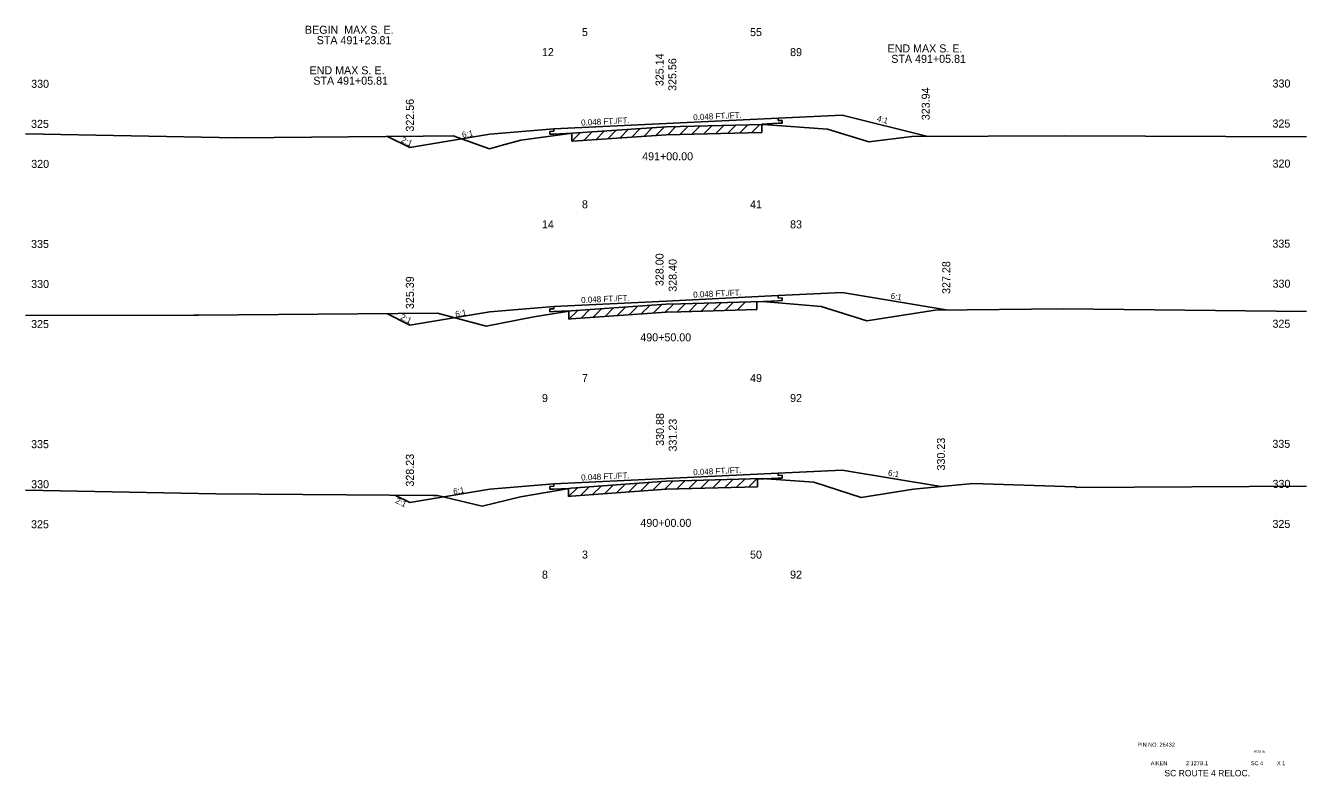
# Model space of a CAD drawing. Extents: x 2967 to 4323, y -3677 to -817.
# Drawn here: x 3188.8 to 3348.8, y -3580.8 to -3487.1 of the extents above; entities that cross this region are included whole.
import ezdxf

# ---------------------------------------------------------------- set-up
doc = ezdxf.new("R2010")
doc.units = 0
for name, color, linetype in [('Level 1', 7, 'Continuous'), ('Level 10', 7, 'Continuous'), ('Level 11', 7, 'Continuous'), ('Level 12', 7, 'Continuous'), ('Level 20', 7, 'Continuous'), ('Level 3', 7, 'Continuous'), ('Level 32', 7, 'Continuous'), ('Level 33', 7, 'Continuous'), ('Level 59', 7, 'Continuous'), ('Level 6', 7, 'Continuous'), ('Level 60', 7, 'Continuous'), ('Level 61', 7, 'Continuous'), ('Level 7', 7, 'Continuous')]:
    doc.layers.add(name, color=color, linetype=linetype)

msp = doc.modelspace()

# ---------------------------------------------------------------- linework, layer by layer
at = {"layer": 'Level 11'}
for p, q in [((3282.76, -3498.91), (3282.76, -3498.61)), ((3283.26, -3498.88), (3282.76, -3498.91)), ((3283.26, -3499.22), (3283.26, -3498.88)), ((3254.76, -3500.25), (3254.26, -3500.28)), ((3254.26, -3500.28), (3254.26, -3500.62)), ((3254.26, -3500.62), (3254.76, -3500.59)), ((3254.76, -3499.95), (3254.76, -3500.25)), ((3282.76, -3499.25), (3283.26, -3499.22)), ((3282.76, -3521.07), (3282.76, -3520.77)), ((3283.26, -3521.05), (3282.76, -3521.07)), ((3282.76, -3521.41), (3283.26, -3521.39)), ((3283.26, -3521.39), (3283.26, -3521.05)), ((3254.76, -3522.42), (3254.26, -3522.44)), ((3254.26, -3522.44), (3254.26, -3522.78)), ((3254.26, -3522.78), (3254.76, -3522.76)), ((3254.76, -3522.12), (3254.76, -3522.42)), ((3282.76, -3543.24), (3282.76, -3542.94)), ((3283.26, -3543.21), (3282.76, -3543.24)), ((3282.76, -3543.58), (3283.26, -3543.55)), ((3283.26, -3543.55), (3283.26, -3543.21)), ((3254.76, -3544.58), (3254.26, -3544.61)), ((3254.26, -3544.61), (3254.26, -3544.95)), ((3254.26, -3544.95), (3254.76, -3544.92)), ((3254.76, -3544.28), (3254.76, -3544.58))]:
    msp.add_line(p, q, dxfattribs=at)
at = {"layer": 'Level 12'}
for p, q in [((3256.98, -3500.49), (3254.76, -3500.59)), ((3256.98, -3500.5), (3256.98, -3500.49)), ((3280.72, -3499.35), (3282.76, -3499.25)), ((3280.72, -3499.39), (3280.72, -3499.35)), ((3280.12, -3521.54), (3282.76, -3521.41)), ((3280.12, -3521.52), (3280.12, -3521.54)), ((3256.64, -3522.67), (3254.76, -3522.76)), ((3256.64, -3522.71), (3256.64, -3522.67)), ((3280.17, -3543.7), (3282.76, -3543.58)), ((3280.17, -3543.64), (3280.17, -3543.7)), ((3256.58, -3544.84), (3254.76, -3544.92)), ((3256.58, -3544.87), (3256.58, -3544.84))]:
    msp.add_line(p, q, dxfattribs=at)
at = {"layer": 'Level 59'}
for p, q in [((3268.76, -3499.28), (3282.76, -3498.61)), ((3254.76, -3499.95), (3268.76, -3499.28)), ((3254.76, -3522.12), (3268.76, -3521.45)), ((3268.76, -3521.45), (3282.76, -3520.77)), ((3254.76, -3544.28), (3268.76, -3543.61)), ((3268.76, -3543.61), (3282.76, -3542.94))]:
    msp.add_line(p, q, dxfattribs=at)
at = {"layer": 'Level 6'}
for p, q in [((3282.76, -3498.61), (3290.76, -3498.22)), ((3246.76, -3500.62), (3254.76, -3499.95)), ((3282.76, -3520.77), (3290.76, -3520.39)), ((3246.76, -3522.78), (3254.76, -3522.12)), ((3282.76, -3542.94), (3290.76, -3542.55)), ((3246.76, -3544.95), (3254.76, -3544.28))]:
    msp.add_line(p, q, dxfattribs=at)
at = {"layer": 'Level 60'}
for p, q in [((3188.76, -3500.58), (3215.13, -3501.08)), ((3250.62, -3501.34), (3257.09, -3500.49)), ((3257.09, -3500.49), (3265.68, -3499.91)), ((3265.68, -3499.91), (3268.82, -3499.7)), ((3268.82, -3499.7), (3280.89, -3499.39)), ((3280.89, -3499.39), (3288.93, -3499.98)), ((3288.93, -3499.98), (3294.11, -3501.57)), ((3215.13, -3501.08), (3238.42, -3500.85)), ((3238.42, -3500.85), (3242.19, -3500.82)), ((3242.19, -3500.82), (3246.73, -3502.44)), ((3246.73, -3502.44), (3248.17, -3502.03)), ((3248.17, -3502.03), (3250.62, -3501.34)), ((3294.11, -3501.57), (3299.48, -3500.91)), ((3299.48, -3500.91), (3318.6, -3500.81)), ((3318.6, -3500.81), (3348.76, -3500.96)), ((3270.6, -3521.79), (3280.8, -3521.5)), ((3280.8, -3521.5), (3288.14, -3522.12)), ((3210.38, -3523.22), (3240.23, -3522.95)), ((3240.23, -3522.95), (3246.31, -3524.6)), ((3252.25, -3523.42), (3256.92, -3522.66)), ((3256.92, -3522.66), (3268.76, -3521.84)), ((3268.76, -3521.84), (3270.6, -3521.79)), ((3288.14, -3522.12), (3293.83, -3523.91)), ((3293.83, -3523.91), (3302.38, -3522.57)), ((3302.38, -3522.57), (3318.4, -3522.43)), ((3318.4, -3522.43), (3348.76, -3522.75)), ((3188.76, -3523.27), (3209.77, -3523.2)), ((3209.77, -3523.2), (3210.38, -3523.22)), ((3246.31, -3524.6), (3252.25, -3523.42)), ((3256.91, -3544.81), (3268.76, -3543.96)), ((3268.76, -3543.96), (3271.99, -3543.87)), ((3271.99, -3543.87), (3280.71, -3543.62)), ((3280.71, -3543.62), (3287.23, -3544.05)), ((3188.76, -3545.08), (3212.53, -3545.52)), ((3212.53, -3545.52), (3239.68, -3545.72)), ((3250.6, -3545.91), (3256.91, -3544.81)), ((3287.23, -3544.05), (3293.16, -3545.99)), ((3293.16, -3545.99), (3299.66, -3544.95)), ((3299.66, -3544.95), (3307.07, -3544.23)), ((3307.07, -3544.23), (3319.86, -3544.64)), ((3319.86, -3544.64), (3320.08, -3544.75)), ((3320.08, -3544.75), (3348.76, -3544.57)), ((3239.68, -3545.72), (3240.23, -3545.71)), ((3240.23, -3545.71), (3245.78, -3547.08)), ((3245.78, -3547.08), (3250.6, -3545.91))]:
    msp.add_line(p, q, dxfattribs=at)
at = {"layer": 'Level 61'}
for p, q in [((3258.06, -3500.42), (3256.98, -3501.5)), ((3256.98, -3500.5), (3256.98, -3501.5)), ((3259.55, -3500.32), (3258.48, -3501.4)), ((3261.05, -3500.22), (3259.98, -3501.3)), ((3262.55, -3500.12), (3261.48, -3501.2)), ((3264.05, -3500.02), (3262.98, -3501.09)), ((3265.55, -3499.92), (3264.48, -3500.99)), ((3265.68, -3500.91), (3268.82, -3500.7)), ((3267.05, -3499.82), (3265.98, -3500.89)), ((3268.55, -3499.72), (3267.48, -3500.79)), ((3268.82, -3500.7), (3280.72, -3500.39)), ((3270, -3499.67), (3268.98, -3500.7)), ((3271.5, -3499.63), (3270.48, -3500.66)), ((3273, -3499.59), (3271.98, -3500.62)), ((3274.5, -3499.55), (3273.48, -3500.58)), ((3276, -3499.52), (3274.98, -3500.54)), ((3277.5, -3499.48), (3276.48, -3500.5)), ((3279, -3499.44), (3277.98, -3500.46)), ((3280.5, -3499.4), (3279.48, -3500.42)), ((3280.72, -3500.39), (3280.72, -3499.39)), ((3256.98, -3501.5), (3257.09, -3501.49)), ((3257.09, -3501.49), (3265.68, -3500.91)), ((3278.67, -3521.56), (3277.64, -3522.59)), ((3280.12, -3522.52), (3280.12, -3521.52)), ((3257.75, -3522.61), (3256.64, -3523.71)), ((3256.64, -3522.71), (3256.64, -3523.71)), ((3256.92, -3523.66), (3268.76, -3522.84)), ((3259.22, -3522.5), (3258.14, -3523.58)), ((3260.72, -3522.4), (3259.64, -3523.48)), ((3262.22, -3522.3), (3261.14, -3523.37)), ((3263.72, -3522.19), (3262.64, -3523.27)), ((3265.22, -3522.09), (3264.14, -3523.16)), ((3266.72, -3521.99), (3265.64, -3523.06)), ((3268.22, -3521.88), (3267.14, -3522.96)), ((3269.68, -3521.82), (3268.64, -3522.85)), ((3268.76, -3522.84), (3270.6, -3522.79)), ((3271.17, -3521.78), (3270.14, -3522.8)), ((3270.6, -3522.79), (3280.12, -3522.52)), ((3272.67, -3521.73), (3271.64, -3522.76)), ((3274.17, -3521.69), (3273.14, -3522.72)), ((3275.67, -3521.65), (3274.64, -3522.68)), ((3277.17, -3521.61), (3276.14, -3522.63)), ((3256.64, -3523.71), (3256.92, -3523.66)), ((3269.61, -3543.94), (3268.58, -3544.98)), ((3271.11, -3543.9), (3270.08, -3544.93)), ((3272.61, -3543.85), (3271.58, -3544.88)), ((3274.11, -3543.81), (3273.08, -3544.84)), ((3275.61, -3543.77), (3274.58, -3544.8)), ((3277.11, -3543.73), (3276.08, -3544.76)), ((3278.61, -3543.68), (3277.58, -3544.71)), ((3280.11, -3543.64), (3279.08, -3544.67)), ((3280.17, -3544.64), (3280.17, -3543.64)), ((3257.69, -3544.76), (3256.58, -3545.87)), ((3256.58, -3544.87), (3256.58, -3545.87)), ((3256.91, -3545.81), (3268.76, -3544.96)), ((3259.15, -3544.65), (3258.08, -3545.73)), ((3260.65, -3544.55), (3259.58, -3545.62)), ((3262.15, -3544.44), (3261.08, -3545.52)), ((3263.65, -3544.33), (3262.58, -3545.41)), ((3265.15, -3544.22), (3264.08, -3545.3)), ((3266.65, -3544.12), (3265.58, -3545.19)), ((3268.15, -3544.01), (3267.08, -3545.09)), ((3268.76, -3544.96), (3271.99, -3544.87)), ((3271.99, -3544.87), (3280.17, -3544.64)), ((3256.58, -3545.87), (3256.91, -3545.81))]:
    msp.add_line(p, q, dxfattribs=at)
at = {"layer": 'Level 7'}
for p, q in [((3290.76, -3498.22), (3301.45, -3500.9)), ((3236.76, -3502.29), (3246.76, -3500.62)), ((3233.98, -3500.9), (3236.76, -3502.29)), ((3290.76, -3520.39), (3303.77, -3522.56)), ((3233.87, -3523.01), (3236.76, -3524.45)), ((3236.76, -3524.45), (3246.76, -3522.78)), ((3290.76, -3542.55), (3303.11, -3544.61)), ((3236.76, -3546.62), (3246.76, -3544.95)), ((3234.89, -3545.68), (3236.76, -3546.62))]:
    msp.add_line(p, q, dxfattribs=at)

# ---------------------------------------------------------------- texts
at = {"layer": 'Level 1'}
for s, p in [('BEGIN  MAX S. E.', (3223.65, -3488.07)), ('5', (3258.26, -3488.36)), ('55', (3279.26, -3488.36)), ('STA 491+23.81', (3225.12, -3489.37)), ('END MAX S. E.', (3296.43, -3490.4)), ('12', (3253.26, -3490.86)), ('89', (3284.26, -3490.86)), ('STA 491+05.81', (3296.9, -3491.7)), ('END MAX S. E.', (3224.23, -3493.13)), ('STA 491+05.81', (3224.7, -3494.43)), ('8', (3258.26, -3509.87)), ('41', (3279.26, -3509.87)), ('14', (3253.26, -3512.37)), ('83', (3284.26, -3512.37)), ('7', (3258.26, -3531.56)), ('49', (3279.26, -3531.56)), ('9', (3253.26, -3534.06)), ('92', (3284.26, -3534.06)), ('3', (3258.26, -3553.61)), ('50', (3279.26, -3553.61)), ('8', (3253.26, -3556.11)), ('92', (3284.26, -3556.11))]:
    msp.add_text(s, height=1, dxfattribs=at).set_placement(p)
at = {"layer": 'Level 10'}
for s, p in [('325.14', (3268.45, -3494.61)), ('328.00', (3268.45, -3519.58)), ('330.88', (3268.5, -3539.53))]:
    msp.add_text(s, height=1, rotation=90, dxfattribs=at).set_placement(p)
for s, p in [('491+00.00', (3265.78, -3503.87)), ('490+50.00', (3265.55, -3526.48)), ('490+00.00', (3265.56, -3549.65))]:
    msp.add_text(s, height=1, dxfattribs=at).set_placement(p)
at = {"layer": 'Level 20'}
for s, height, p in [('PIN NO. 26432', 0.5, (3327.65, -3577.1)), ('ROUTE', 0.3, (3342.19, -3577.84)), ('AIKEN', 0.5, (3329.31, -3579.41)), (' 2.127B.1', 0.5, (3333.53, -3579.41)), ('SC 4', 0.5, (3341.82, -3579.41)), ('X 1', 0.5, (3345.08, -3579.41)), ('SC ROUTE 4 RELOC.', 0.8, (3331.02, -3580.8))]:
    msp.add_text(s, height=height, dxfattribs=at).set_placement(p)
at = {"layer": 'Level 3'}
for s, p in [(' 330', (3189.08, -3494.82)), (' 330', (3344.16, -3494.78)), (' 325', (3189.07, -3499.82)), (' 325', (3344.15, -3499.78)), (' 320', (3189.09, -3504.82)), (' 320', (3344.16, -3504.78)), (' 335', (3189.07, -3514.82)), (' 335', (3344.14, -3514.78)), (' 330', (3189.08, -3519.82)), (' 330', (3344.16, -3519.78)), (' 325', (3189.07, -3524.82)), (' 325', (3344.15, -3524.78)), (' 335', (3189.07, -3539.82)), (' 335', (3344.14, -3539.78)), (' 330', (3189.08, -3544.82)), (' 330', (3344.16, -3544.78)), (' 325', (3344.15, -3549.78)), (' 325', (3189.07, -3549.82))]:
    msp.add_text(s, height=1, dxfattribs=at).set_placement(p)
at = {"layer": 'Level 32'}
for s, rotation, p in [('0.048 FT./FT.', 2.7481, (3258.17, -3499.54)), ('0.048 FT./FT.', 2.748, (3272.17, -3498.87)), ('4:1', 345.9638, (3295.06, -3498.98)), ('6:1', 9.4623, (3243.34, -3501.07)), ('2:1', 333.435, (3235.59, -3501.56)), ('0.048 FT./FT.', 2.7481, (3258.17, -3521.7)), ('0.048 FT./FT.', 2.748, (3272.17, -3521.03)), ('6:1', 350.5377, (3296.78, -3521.14)), ('2:1', 333.435, (3235.5, -3523.68)), ('6:1', 9.4623, (3242.5, -3523.46)), ('0.048 FT./FT.', 2.748, (3272.17, -3543.2)), ('0.048 FT./FT.', 2.7481, (3258.17, -3543.87)), ('6:1', 350.5377, (3296.45, -3543.25)), ('6:1', 9.4623, (3242.24, -3545.62)), ('2:1', 333.435, (3234.87, -3546.61))]:
    msp.add_text(s, height=0.75, rotation=rotation, dxfattribs=at).set_placement(p)
at = {"layer": 'Level 33'}
for s, p in [('323.94', (3301.7, -3498.87)), ('322.56', (3237.26, -3500.29)), ('327.28', (3304.27, -3520.56)), ('325.39', (3237.26, -3522.45)), ('330.23', (3303.61, -3542.61)), ('328.23', (3237.26, -3544.62))]:
    msp.add_text(s, height=1, rotation=90, dxfattribs=at).set_placement(p)
at = {"layer": 'Level 59'}
for s, p in [(' 325.56', (3270.05, -3495.58)), (' 328.40', (3270.09, -3520.66)), (' 331.23', (3270.1, -3540.61))]:
    msp.add_text(s, height=1, rotation=90, dxfattribs=at).set_placement(p)

doc.saveas('drawing.dxf')
